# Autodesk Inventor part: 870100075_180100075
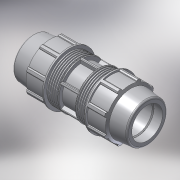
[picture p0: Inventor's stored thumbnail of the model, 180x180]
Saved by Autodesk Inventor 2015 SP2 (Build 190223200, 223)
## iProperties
Created: 2017-02
Part Number: 870100075_180100075
Material: PVC-Piping
Description: PLASSON COUPLER 75-75
Document SubType Name: Modeling
Designer: KIM
Mass: 2387.75 g
Surface Area: 2478.17 cm^2
Volume: 1705.54 cm^3
Density: 1.4 g/cm^3
Appearance: Smooth - White
Author: KIM
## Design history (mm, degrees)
derived "87010.ipt"
feature "Solid1::87010.ipt"
tag "TaggingFeature1"
body "Solid1"
other parameters: "d1" = 289, "d2" = 75, "d4" = 24.08333, "d5" = 41.28571, "d7" = 132, "d8" = 99, "d9" = 41.28571, "d11" = 4.12857, "d12" = 105.6, "d13" = 120 deg, "d14" = 105, "d15" = 6 deg, "d16" = 118.8, "d18" = 3.75, "d19" = 35 deg, "d20" = 17.5 deg, "d21" = 122.76, "d23" = 0, "d25" = 360 deg, "d27" = 2.64, "d33" = 1.5, "d34" = 6.6, "d36" = 0, "d37" = 1.5, "d38" = 1.5, "d40" = 360 deg, "d42" = 52.02, "d46" = 2.25, "d50" = 3.6125, "d51" = 0, "d53" = 2.64229, "d54" = 2.64229, "d57" = 5.28457, "d62" = 116.424, "d64" = 67.5, "d65" = 143, "d_" = 75, "E_" = 132, "H_" = 289, "l_" = 143, "d52" = 26.42286
